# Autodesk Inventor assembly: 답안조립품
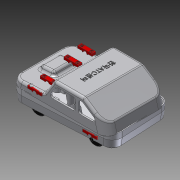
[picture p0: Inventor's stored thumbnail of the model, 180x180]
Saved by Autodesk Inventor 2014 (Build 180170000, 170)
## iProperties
Created: 2015-05
Part Number: 답안조립품
Document SubType Name: Assembly
Designer: Administrator
Author: Administrator
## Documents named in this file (5)
- C:\Documents and Settings\Administrator\바탕 화면\450508V1014\답안조립품.iam
- C:\Documents and Settings\Administrator\바탕 화면\450508V1014\본체.ipt
- C:\Documents and Settings\Administrator\바탕 화면\450508V1014\커버.ipt
- C:\Documents and Settings\Administrator\바탕 화면\450508V1014\바퀴고정부.ipt
- C:\Documents and Settings\Administrator\바탕 화면\450508V1014\바퀴.ipt
